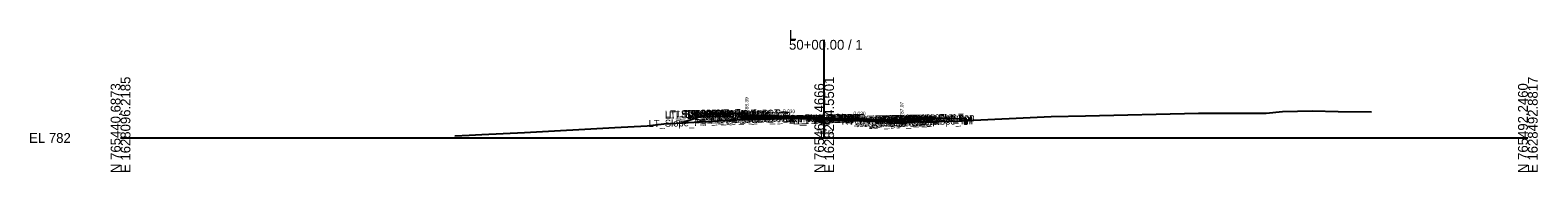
# Model space of a CAD drawing. Extents: x -26 to 4403, y -510 to 9556.
# Drawn here: x 3974.3 to 4402.8, y -9.7 to 30.8 of the extents above; entities that cross this region are included whole.
import ezdxf

# ---------------------------------------------------------------- set-up
doc = ezdxf.new("R2010")
doc.units = 0
for name, color, linetype in [('Default', 7, 'Continuous'), ('Exist CMT Pavement', 7, 'Continuous'), ('Exist Cross Section Cell', 7, 'Continuous'), ('Exist XS Center Line Elevation Label', 7, 'Continuous'), ('Exist XS Ground Line', 7, 'Continuous'), ('Prop CMT Conc Surface', 7, 'Continuous'), ('Prop CMT Concrete Structures', 7, 'Continuous'), ('Prop CMT Pvmt Course 1', 7, 'Continuous'), ('Prop CMT Pvmt Course 1 CG', 7, 'Continuous'), ('Prop CMT Pvmt Course 1 Wedge', 7, 'Continuous'), ('Prop CMT Pvmt Course 2', 7, 'Continuous'), ('Prop CMT Pvmt Course 2 Wedge', 7, 'Continuous'), ('Prop CMT Pvmt Course 3', 7, 'Continuous'), ('Prop CMT Pvmt Course 3 Wedge', 7, 'Continuous'), ('Prop CMT Pvmt Surface', 7, 'Continuous'), ('Prop CMT Pvmt Wedge Surface 1', 7, 'Continuous'), ('Prop CMT Pvmt Wedge Surface 2', 7, 'Continuous'), ('Prop CMT Pvmt Wedge Surface 3', 7, 'Continuous'), ('Prop CMT Slope Grass', 7, 'Continuous'), ('Prop CMT Subgrade Earthwork', 7, 'Continuous'), ('Prop XS Finish Grade CurbGutter', 7, 'Continuous'), ('Prop XS Hydro Elevations', 7, 'Continuous'), ('Prop XS SE Text', 7, 'Continuous'), ('Prop XS Side Slope Text', 7, 'Continuous'), ('Scratch_Level_0', 7, 'Continuous')]:
    doc.layers.add(name, color=color, linetype=linetype)

msp = doc.modelspace()

# ---------------------------------------------------------------- linework, layer by layer
at = {"layer": 'Exist CMT Pavement'}
for points in [[(4200, 5.61), (4197.25, 5.63), (4194.19, 5.66), (4184.86, 5.49), (4181.55, 5.41), (4179.98, 5.35)], [(4200, 5.61), (4206.34, 5.58), (4209.31, 5.46), (4218.55, 5.04), (4220.02, 5.08)]]:
    msp.add_lwpolyline(points, dxfattribs=at)
at = {"layer": 'Exist Cross Section Cell'}
for p, q in [((4200, 0), (4200, 27.97)), ((4000, 0), (4200, 0)), ((4200, 0), (4400, 0))]:
    msp.add_line(p, q, dxfattribs=at)
at = {"layer": 'Exist XS Ground Line'}
msp.add_lwpolyline([(4095.05, 0.63), (4099.11, 0.76), (4102.68, 0.94), (4114.85, 1.6), (4140.45, 2.95), (4149.7, 3.43), (4154.4, 3.99), (4175.13, 5.18), (4178.9, 5.32), (4179.44, 5.34), (4181.55, 5.41), (4184.86, 5.49), (4194.19, 5.66), (4197.25, 5.63), (4200, 5.61), (4206.34, 5.58), (4209.31, 5.46), (4218.55, 5.04), (4222.5, 5.06), (4223.01, 4.79), (4226.06, 4.69), (4226.56, 4.68), (4227.13, 4.68), (4231.56, 4.66), (4238.54, 4.9), (4264.54, 6.08), (4274.3, 6.29), (4306.43, 7.09), (4325.66, 7.08), (4330.27, 7.56), (4338.82, 7.76), (4346.1, 7.51), (4355.6, 7.42)], dxfattribs=at)
at = {"layer": 'Prop CMT Conc Surface'}
for points in [[(4173.46, 6.98), (4168.46, 7.08)], [(4177.96, 6.39), (4177.96, 6.89), (4177.46, 6.89)], [(4179.96, 6.41), (4177.96, 6.39)], [(4220.04, 5.21), (4222.04, 5.07)], [(4222.04, 5.07), (4222.04, 5.57), (4222.54, 5.57)], [(4226.54, 5.66), (4231.54, 5.76)]]:
    msp.add_lwpolyline(points, dxfattribs=at)
at = {"layer": 'Prop CMT Concrete Structures'}
for points in [[(4168.46, 6.75), (4168.46, 7.08)], [(4168.46, 7.08), (4173.46, 6.98)], [(4173.46, 6.64), (4168.46, 6.75)], [(4173.46, 6.98), (4173.46, 6.64)], [(4179.96, 6.41), (4177.96, 6.39), (4177.96, 6.89), (4177.46, 6.89)], [(4177.46, 6.89), (4177.46, 5.9), (4179.96, 5.83)], [(4179.96, 5.83), (4179.96, 6.41)], [(4220.04, 5.21), (4222.04, 5.07), (4222.04, 5.57), (4222.54, 5.57)], [(4222.54, 5.57), (4222.54, 4.55), (4220.04, 4.62)], [(4220.04, 4.62), (4220.04, 5.21)], [(4231.54, 5.76), (4226.54, 5.66)], [(4226.54, 5.66), (4226.54, 5.32)], [(4226.54, 5.32), (4231.54, 5.42)], [(4231.54, 5.42), (4231.54, 5.76)]]:
    msp.add_lwpolyline(points, dxfattribs=at)
at = {"layer": 'Prop CMT Pvmt Course 1'}
for points in [[(4200, 5.81), (4179.96, 6.41)], [(4179.96, 6.41), (4179.96, 6.16), (4179.96, 6.16), (4179.96, 6.28)], [(4179.96, 6.28), (4200, 5.68)], [(4200, 5.81), (4220.04, 5.21)], [(4200, 5.56), (4200, 5.81)], [(4200, 5.56), (4200, 5.81)], [(4220.04, 5.08), (4200, 5.68)], [(4200, 5.68), (4200, 5.56), (4200, 5.56)], [(4200, 5.68), (4200, 5.56), (4200, 5.56)], [(4220.04, 5.21), (4220.04, 4.96), (4220.04, 4.96), (4220.04, 5.08)]]:
    msp.add_lwpolyline(points, dxfattribs=at)
at = {"layer": 'Prop CMT Pvmt Course 1 CG'}
for points in [[(4179.96, 5.83), (4176.96, 5.91), (4176.64, 5.59)], [(4176.64, 5.59), (4179.96, 5.49)], [(4179.96, 5.49), (4179.96, 5.83)], [(4220.04, 4.62), (4223.04, 4.53), (4223.38, 4.19)], [(4220.04, 4.29), (4220.04, 4.62)], [(4223.38, 4.19), (4220.04, 4.29)]]:
    msp.add_lwpolyline(points, dxfattribs=at)
at = {"layer": 'Prop CMT Pvmt Course 1 Wedge'}
for points in [[(4179.96, 6.28), (4181.55, 6.24), (4184.86, 6.14), (4194.19, 5.86), (4197.25, 5.76), (4200, 5.68)], [(4179.96, 6.16), (4179.96, 6.28)], [(4200, 5.61), (4197.6, 5.63), (4197.25, 5.64), (4194.19, 5.73), (4184.86, 6.01), (4181.55, 6.11), (4179.96, 6.16)], [(4200, 5.68), (4200, 5.61)], [(4200, 5.68), (4202.82, 5.6)], [(4200, 5.61), (4200, 5.68)], [(4202.82, 5.6), (4200, 5.61)], [(4220, 5.08), (4218.55, 5.04), (4213.15, 5.29)], [(4213.15, 5.29), (4218.55, 5.13)], [(4218.55, 5.13), (4220, 5.08)]]:
    msp.add_lwpolyline(points, dxfattribs=at)
at = {"layer": 'Prop CMT Pvmt Course 2'}
for points in [[(4179.96, 5.83), (4179.96, 5.83), (4179.96, 6.16), (4179.96, 6.16)], [(4179.96, 6.16), (4179.96, 5.83)], [(4220.04, 4.62), (4220.04, 4.62), (4220.04, 4.96), (4220.04, 4.96)], [(4220.04, 4.96), (4220.04, 4.62)]]:
    msp.add_lwpolyline(points, dxfattribs=at)
at = {"layer": 'Prop CMT Pvmt Course 2 Wedge'}
for points in [[(4179.96, 6.16), (4181.55, 6.11), (4184.86, 6.01), (4194.19, 5.73), (4197.25, 5.64), (4197.6, 5.63)], [(4179.96, 5.82), (4179.96, 6.16)], [(4197.6, 5.63), (4197.25, 5.63), (4194.19, 5.66), (4188.75, 5.56), (4184.86, 5.68), (4181.55, 5.78), (4179.96, 5.82)]]:
    msp.add_lwpolyline(points, dxfattribs=at)
at = {"layer": 'Prop CMT Pvmt Course 3'}
for points in [[(4179.96, 5.83), (4179.96, 5.83), (4179.96, 5.49), (4179.96, 5.49)], [(4179.96, 5.49), (4179.96, 5.83)], [(4220.04, 4.62), (4220.04, 4.62), (4220.04, 4.29), (4220.04, 4.29)], [(4220.04, 4.29), (4220.04, 4.62)]]:
    msp.add_lwpolyline(points, dxfattribs=at)
at = {"layer": 'Prop CMT Pvmt Course 3 Wedge'}
for points in [[(4179.96, 5.83), (4181.55, 5.78), (4184.86, 5.68), (4188.76, 5.56)], [(4179.96, 5.35), (4179.96, 5.83)], [(4188.76, 5.56), (4184.86, 5.49), (4181.55, 5.41), (4179.96, 5.35)]]:
    msp.add_lwpolyline(points, dxfattribs=at)
at = {"layer": 'Prop CMT Pvmt Surface'}
for points in [[(4200, 5.81), (4179.96, 6.41)], [(4200, 5.81), (4220.04, 5.21)]]:
    msp.add_lwpolyline(points, dxfattribs=at)
at = {"layer": 'Prop CMT Pvmt Wedge Surface 1'}
for points in [[(4179.96, 6.16), (4179.96, 6.41)], [(4200, 5.68), (4179.96, 6.28)], [(4179.96, 6.28), (4179.96, 6.16), (4179.96, 6.16)], [(4200, 5.68), (4220.04, 5.08)], [(4220.04, 4.96), (4220.04, 5.21)], [(4220.04, 5.08), (4220.04, 4.96), (4220.04, 4.96)]]:
    msp.add_lwpolyline(points, dxfattribs=at)
at = {"layer": 'Prop CMT Pvmt Wedge Surface 2'}
for points in [[(4179.96, 6.16), (4179.96, 6.41)], [(4200, 5.56), (4179.96, 6.16)], [(4200, 5.56), (4220.04, 4.96)], [(4220.04, 4.96), (4220.04, 5.21)]]:
    msp.add_lwpolyline(points, dxfattribs=at)
at = {"layer": 'Prop CMT Pvmt Wedge Surface 3'}
for points in [[(4179.96, 5.83), (4179.96, 6.41)], [(4200, 5.22), (4179.96, 5.83)], [(4200, 5.22), (4220.04, 4.62)], [(4220.04, 4.62), (4220.04, 5.21)]]:
    msp.add_lwpolyline(points, dxfattribs=at)
at = {"layer": 'Prop CMT Slope Grass'}
for p, q in [((4222.54, 5.57), (4232.05, 5.76)), ((4232.05, 5.76), (4239.88, 5.49))]:
    msp.add_line(p, q, dxfattribs=at)
for points in [[(4177.46, 6.89), (4167.95, 7.08), (4159.58, 4.29)], [(4239.88, 5.49), (4239.88, 4), (4240.54, 4), (4240.54, 4.99)]]:
    msp.add_lwpolyline(points, dxfattribs=at)
at = {"layer": 'Prop CMT Subgrade Earthwork'}
for points in [[(4179.96, 5.49), (4176.64, 5.59), (4175.3, 6.93)], [(4179.96, 5.49), (4179.96, 5.49)], [(4179.96, 5.49), (4179.98, 5.35)], [(4220.04, 4.29), (4220.02, 5.08)], [(4220.04, 4.29), (4223.38, 4.19), (4224.8, 5.61)], [(4220.04, 4.29), (4220.04, 4.29)]]:
    msp.add_lwpolyline(points, dxfattribs=at)
at = {"layer": 'Prop XS Finish Grade CurbGutter'}
for p, q in [((4239.88, 5.49), (4240.07, 5.49)), ((4239.88, 5.49), (4240.54, 5.49)), ((4239.88, 5.49), (4239.88, 4.5)), ((4239.88, 4.5), (4239.88, 4)), ((4239.88, 4.5), (4240.54, 4.5)), ((4240.54, 5.08), (4240.19, 5.44)), ((4240.54, 5.08), (4240.54, 4.5)), ((4240.54, 4.99), (4240.54, 4.99)), ((4240.54, 4.5), (4240.54, 4)), ((4239.88, 4), (4240.54, 4))]:
    msp.add_line(p, q, dxfattribs=at)
msp.add_arc((4240.07, 5.33), 0.166, 43.9997, 90, dxfattribs=at)

# ---------------------------------------------------------------- texts
at = {"layer": 'Default'}
msp.add_text('-', height=0.0001, dxfattribs=at).set_placement((4000, 0))
at = {"layer": 'Exist Cross Section Cell'}
for s, p in [('L', (4190, 27.97)), ('50+00.00 / 1', (4190, 25.17)), ('EL 782', (3974, -1.4))]:
    msp.add_text(s, height=2.8, dxfattribs=at).set_placement(p)
for s, p in [('E 1628096.2185', (4002.8, -10)), ('E 1628294.5501', (4202.8, -10)), ('E 1628492.8817', (4402.8, -10)), ('N 765440.6873', (4000, -10)), ('N 765466.4666', (4200, -10)), ('N 765492.2460', (4400, -10))]:
    msp.add_text(s, height=2.8, rotation=90, dxfattribs=at).set_placement(p)
at = {"layer": 'Exist XS Center Line Elevation Label'}
msp.add_text('787.61', height=1.2, dxfattribs=at).set_placement((4197.79, 1.01))
at = {"layer": 'Prop XS Hydro Elevations'}
for s, p in [('788.39', (4178.46, 7.39)), ('787.07', (4222.54, 6.07))]:
    msp.add_text(s, height=1, rotation=90, dxfattribs=at).set_placement(p)
at = {"layer": 'Prop XS SE Text'}
for rotation, p in [(358.282, (4188.26, 7.16)), (358.2821, (4208.3, 6.56))]:
    msp.add_text('0.030', height=1, rotation=rotation, dxfattribs=at).set_placement(p)
at = {"layer": 'Prop XS Side Slope Text'}
for s, rotation, p in [('3:1', 18.4372, (4162.78, 6.14)), ('VAR.', 358.0831, (4234.7, 5.8))]:
    msp.add_text(s, height=1, rotation=rotation, dxfattribs=at).set_placement(p)
at = {"layer": 'Scratch_Level_0'}
for s, p in [('LT_Slope_Fill', (4150.12, 3.1)), ('LT_SDWK_Out_Top', (4154.72, 5.8)), ('LT_SDWK_Out_Bot', (4154.75, 5.47)), ('LT_Sub_Trench_Out_DLT', (4155.89, 5.54)), ('LT_CSLP_Pnt', (4158.15, 5.88)), ('50+00.00', (4160.45, 5.74)), ('LT_SDWK_In_Top', (4161.34, 5.74)), ('LT_SDWK_In_Bot', (4161.37, 5.4)), ('50+00.00', (4162.09, 5.93)), ('LT_CG1_Shelf_Out', (4163.54, 4.65)), ('LT_PV_Sub_Tie_Out', (4164.94, 4.05)), ('LT_CG_Top_Face', (4165.24, 5.63)), ('LT_CG_Top_BOC', (4165.77, 5.65)), ('LT_CG_Bot_BOC', (4165.8, 4.67)), ('LT_CG_Top_Gut', (4166.22, 5.15)), ('LT_Sub_OEOP', (4166.77, 4.39)), ('LT_PV_OEEOP_EG', (4167.53, 4.11)), ('50+00.00', (4167.69, 5.81)), ('50+00.00', (4169.22, 5.78)), ('LT_Sub_OEEOP', (4169.2, 4.28)), ('LT_PV2_OEEOP', (4169.29, 4.94)), ('LT_PV3_OEEOP', (4169.29, 4.61)), ('LT_PV1_OEEOP', (4169.86, 5.08)), ('LT_CG_Bot_IE', (4169.9, 4.62)), ('LT_Sub_OEOT', (4170.06, 4.29)), ('LT_PV2_OEOT', (4170.16, 4.96)), ('LT_PV3_OEOT', (4170.16, 4.63)), ('LT_PV1_OEOT', (4170.72, 5.22)), ('50+00.00', (4170.97, 5.75)), ('50+00.00', (4171.07, 5.34)), ('50+00.00', (4171.46, 5.25)), ('RT_PV_IEEOP_EG', (4188.16, 4.38)), ('LT_PV_IEEOP_EG', (4188.21, 4.38)), ('RT_PV2_IEEOP', (4189.93, 4.36)), ('RT_PV3_IEEOP', (4189.93, 4.02)), ('LT_PV2_IEEOP', (4189.97, 4.36)), ('LT_PV3_IEEOP', (4189.97, 4.02)), ('RT_PV1_IEEOP', (4190.49, 4.49)), ('LT_PV1_IEEOP', (4190.54, 4.49)), ('PV2_PGL', (4193.93, 4.44)), ('PV1_PGL', (4194.49, 4.7)), ('RT_PV_Sub_Tie_Out', (4204.94, 3.78)), ('RT_Sub_Trench_Out_DLT', (4205.35, 4.22)), ('RT_PV_OEEOP_EG', (4207.56, 3.83)), ('RT_Sub_OEEOP', (4209.23, 3.07)), ('RT_CG_Top_Face', (4209.27, 4.31)), ('RT_PV2_OEEOP', (4209.32, 3.74)), ('RT_PV3_OEEOP', (4209.32, 3.41)), ('RT_CG1_Shelf_Out', (4209.56, 3.26)), ('RT_PV1_OEEOP', (4209.89, 3.88)), ('RT_CG_Bot_IE', (4209.93, 3.42)), ('RT_Sub_OEOT', (4210.09, 3.09)), ('RT_PV2_OEOT', (4210.19, 3.76)), ('RT_PV3_OEOT', (4210.19, 3.43)), ('RT_CG_Top_Gut', (4210.25, 3.83)), ('RT_PV1_OEOT', (4210.75, 4.02)), ('RT_CG_Top_BOC', (4210.8, 4.33)), ('RT_CG_Bot_BOC', (4210.83, 3.31)), ('RT_Sub_OEOP', (4213.47, 2.99)), ('50+00.00', (4214.34, 3.98)), ('RT_SDWK_In_Top', (4214.38, 4.41)), ('RT_SDWK_In_Bot', (4214.41, 4.08)), ('50+00.00', (4215.52, 4.43)), ('RT_SDWK_Out_Top', (4217.76, 4.48)), ('RT_SDWK_Out_Bot', (4217.79, 4.15)), ('50+00.00', (4219.09, 4.5)), ('50+00.00', (4220.67, 4.54)), ('RT_CSLP_Pnt', (4222.2, 4.56)), ('RT_Slope_Fill', (4225.48, 3.59))]:
    msp.add_text(s, height=2, rotation=1.1458, dxfattribs=at).set_placement(p)

doc.saveas('drawing.dxf')
